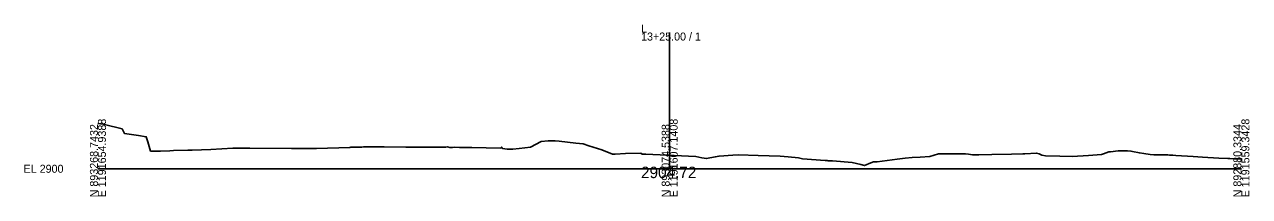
# Model space of a CAD drawing. Extents: x 1791751 to 1799722, y 648637 to 665635.
# Drawn here: x 1792163.2 to 1792591.7, y 655530.3 to 655590.5 of the extents above; entities that cross this region are included whole.
import ezdxf

# ---------------------------------------------------------------- set-up
doc = ezdxf.new("R2010")
doc.units = 0
for name, color, linetype in [('Exist Cross Section Cell', 7, 'Continuous'), ('Exist XS Center Line Elevation Label', 7, 'Continuous'), ('Exist XS Ground Line', 7, 'Continuous')]:
    doc.layers.add(name, color=color, linetype=linetype)

msp = doc.modelspace()

# ---------------------------------------------------------------- linework, layer by layer
at = {"layer": 'Exist Cross Section Cell'}
for p, q in [((1792388.88, 655540.04), (1792388.88, 655587.66)), ((1792388.88, 655540.04), (1792388.88, 655587.66)), ((1792388.88, 655540.04), (1792388.88, 655587.66)), ((1792188.88, 655540.04), (1792388.88, 655540.04)), ((1792188.88, 655540.04), (1792388.88, 655540.04)), ((1792188.88, 655540.04), (1792388.88, 655540.04)), ((1792388.88, 655540.04), (1792588.88, 655540.04)), ((1792388.88, 655540.04), (1792588.88, 655540.04)), ((1792388.88, 655540.04), (1792588.88, 655540.04))]:
    msp.add_line(p, q, dxfattribs=at)
at = {"layer": 'Exist XS Ground Line'}
msp.add_lwpolyline([(1792188.88, 655555.91), (1792190.69, 655555.58), (1792191.19, 655555.46), (1792197.34, 655554.04), (1792198.19, 655552.33), (1792203.02, 655551.62), (1792205.76, 655551.25), (1792206.32, 655549.47), (1792207.31, 655546.21), (1792209.95, 655546.14), (1792210.81, 655546.14), (1792214.08, 655546.32), (1792215.32, 655546.42), (1792220.34, 655546.52), (1792221.87, 655546.58), (1792228.4, 655546.77), (1792236.07, 655547.19), (1792241.98, 655547.23), (1792256.58, 655547.06), (1792257.59, 655547.06), (1792261.05, 655547.1), (1792262.05, 655547.1), (1792264.31, 655547.12), (1792265.39, 655547.11), (1792276.94, 655547.51), (1792277.36, 655547.53), (1792278.62, 655547.55), (1792279.03, 655547.56), (1792280.07, 655547.55), (1792280.6, 655547.56), (1792281.19, 655547.56), (1792281.83, 655547.65), (1792282.95, 655547.65), (1792284.05, 655547.66), (1792285.36, 655547.65), (1792286.45, 655547.65), (1792287.62, 655547.66), (1792288.99, 655547.65), (1792296.59, 655547.63), (1792297.22, 655547.62), (1792297.83, 655547.62), (1792305.24, 655547.56), (1792305.88, 655547.56), (1792310.51, 655547.53), (1792311.19, 655547.67), (1792311.93, 655547.52), (1792312.93, 655547.52), (1792313.51, 655547.53), (1792315.32, 655547.49), (1792316.92, 655547.46), (1792319.62, 655547.42), (1792329.68, 655547.2), (1792330.08, 655547.64), (1792330.42, 655547.06), (1792332.02, 655546.88), (1792332.54, 655546.9), (1792334.01, 655546.88), (1792336.18, 655547.17), (1792340.24, 655547.64), (1792343.93, 655549.58), (1792346.33, 655549.82), (1792348.82, 655549.79), (1792350.24, 655549.69), (1792356.06, 655549.04), (1792358.6, 655548.75), (1792360.59, 655548.03), (1792365.1, 655546.65), (1792368.9, 655545.11), (1792369.77, 655545.15), (1792373.45, 655545.32), (1792378.85, 655545.52), (1792379.31, 655545.17), (1792379.63, 655545.17), (1792380.54, 655545.14), (1792388.01, 655544.8), (1792389.15, 655544.75), (1792390.44, 655544.68), (1792398.01, 655544.3), (1792400.09, 655543.87), (1792401.81, 655543.59), (1792404.81, 655544.18), (1792406.16, 655544.46), (1792411.01, 655544.76), (1792412.91, 655544.88), (1792419.89, 655544.65), (1792427.57, 655544.44), (1792430.34, 655544.18), (1792434, 655543.84), (1792435.3, 655543.53), (1792443.25, 655542.93), (1792443.97, 655542.91), (1792444.38, 655542.85), (1792445.79, 655542.78), (1792452.7, 655542.25), (1792455.71, 655541.53), (1792457.01, 655541.16), (1792459.28, 655542.08), (1792460.17, 655542.43), (1792461.43, 655542.51), (1792468.47, 655543.34), (1792471.23, 655543.71), (1792473.66, 655543.92), (1792476.51, 655544.14), (1792479.9, 655544.28), (1792482.96, 655545.22), (1792490.25, 655545.28), (1792492.33, 655545.29), (1792493.4, 655545.13), (1792494.81, 655544.95), (1792497, 655544.9), (1792501.58, 655544.99), (1792508.45, 655545.16), (1792512.38, 655545.26), (1792513.16, 655545.29), (1792517.26, 655545.51), (1792518.11, 655545.2), (1792519.08, 655544.83), (1792520.39, 655544.5), (1792525.38, 655544.48), (1792529.66, 655544.34), (1792535.37, 655544.72), (1792539.93, 655545.03), (1792540.26, 655545.16), (1792540.66, 655545.26), (1792542.52, 655545.92), (1792543.05, 655545.99), (1792545.79, 655546.29), (1792549.09, 655546.27), (1792550.26, 655546.21), (1792550.75, 655546.11), (1792553.2, 655545.58), (1792554.74, 655545.33), (1792557.01, 655545.04), (1792558.29, 655544.85), (1792563.12, 655544.85), (1792563.76, 655544.8), (1792564.86, 655544.74), (1792565.9, 655544.68), (1792571.98, 655544.31), (1792575.31, 655544.14), (1792580.95, 655543.76), (1792584.14, 655543.62), (1792584.89, 655543.57), (1792586.21, 655543.53), (1792588.88, 655543.52)], dxfattribs=at)
msp.add_lwpolyline([(1792188.88, 655555.91), (1792190.69, 655555.58), (1792191.19, 655555.46), (1792197.34, 655554.04), (1792198.19, 655552.33), (1792203.02, 655551.62), (1792205.76, 655551.25), (1792206.32, 655549.47), (1792207.31, 655546.21), (1792209.95, 655546.14), (1792210.81, 655546.14), (1792214.08, 655546.32), (1792215.32, 655546.42), (1792220.34, 655546.52), (1792221.87, 655546.58), (1792228.4, 655546.77), (1792236.07, 655547.19), (1792241.98, 655547.23), (1792256.58, 655547.06), (1792257.59, 655547.06), (1792261.05, 655547.1), (1792262.05, 655547.1), (1792264.31, 655547.12), (1792265.39, 655547.11), (1792276.94, 655547.51), (1792277.36, 655547.53), (1792278.62, 655547.55), (1792279.03, 655547.56), (1792280.07, 655547.55), (1792280.6, 655547.56), (1792281.19, 655547.56), (1792281.83, 655547.65), (1792282.95, 655547.65), (1792284.05, 655547.66), (1792285.36, 655547.65), (1792286.45, 655547.65), (1792287.62, 655547.66), (1792288.99, 655547.65), (1792296.59, 655547.63), (1792297.22, 655547.62), (1792297.83, 655547.62), (1792305.24, 655547.56), (1792305.88, 655547.56), (1792310.51, 655547.53), (1792311.19, 655547.67), (1792311.93, 655547.52), (1792312.93, 655547.52), (1792313.51, 655547.53), (1792315.32, 655547.49), (1792316.92, 655547.46), (1792319.62, 655547.42), (1792329.68, 655547.2), (1792330.08, 655547.64), (1792330.42, 655547.06), (1792332.02, 655546.88), (1792332.54, 655546.9), (1792334.01, 655546.88), (1792336.18, 655547.17), (1792340.24, 655547.64), (1792343.93, 655549.58), (1792346.33, 655549.82), (1792348.82, 655549.79), (1792350.24, 655549.69), (1792356.06, 655549.04), (1792358.6, 655548.75), (1792360.59, 655548.03), (1792365.1, 655546.65), (1792368.9, 655545.11), (1792369.77, 655545.15), (1792373.45, 655545.32), (1792378.85, 655545.52), (1792379.31, 655545.17), (1792379.63, 655545.17), (1792380.54, 655545.14), (1792388.01, 655544.8), (1792389.15, 655544.75), (1792390.44, 655544.68), (1792398.01, 655544.3), (1792400.09, 655543.87), (1792401.81, 655543.59), (1792404.81, 655544.18), (1792406.16, 655544.46), (1792411.01, 655544.76), (1792412.91, 655544.88), (1792419.89, 655544.65), (1792427.57, 655544.44), (1792430.34, 655544.18), (1792434, 655543.84), (1792435.3, 655543.53), (1792443.25, 655542.93), (1792443.97, 655542.91), (1792444.38, 655542.85), (1792445.79, 655542.78), (1792452.7, 655542.25), (1792455.71, 655541.53), (1792457.01, 655541.16), (1792459.28, 655542.08), (1792460.17, 655542.43), (1792461.43, 655542.51), (1792468.47, 655543.34), (1792471.23, 655543.71), (1792473.66, 655543.92), (1792476.51, 655544.14), (1792479.9, 655544.28), (1792482.96, 655545.22), (1792490.25, 655545.28), (1792492.33, 655545.29), (1792493.4, 655545.13), (1792494.81, 655544.95), (1792497, 655544.9), (1792501.58, 655544.99), (1792508.45, 655545.16), (1792512.38, 655545.26), (1792513.16, 655545.29), (1792517.26, 655545.51), (1792518.11, 655545.2), (1792519.08, 655544.83), (1792520.39, 655544.5), (1792525.38, 655544.48), (1792529.66, 655544.34), (1792535.37, 655544.72), (1792539.93, 655545.03), (1792540.26, 655545.16), (1792540.66, 655545.26), (1792542.52, 655545.92), (1792543.05, 655545.99), (1792545.79, 655546.29), (1792549.09, 655546.27), (1792550.26, 655546.21), (1792550.75, 655546.11), (1792553.2, 655545.58), (1792554.74, 655545.33), (1792557.01, 655545.04), (1792558.29, 655544.85), (1792563.12, 655544.85), (1792563.76, 655544.8), (1792564.86, 655544.74), (1792565.9, 655544.68), (1792571.98, 655544.31), (1792575.31, 655544.14), (1792580.95, 655543.76), (1792584.14, 655543.62), (1792584.89, 655543.57), (1792586.21, 655543.53), (1792588.88, 655543.52)], dxfattribs=at)
msp.add_lwpolyline([(1792188.88, 655555.91), (1792190.69, 655555.58), (1792191.19, 655555.46), (1792197.34, 655554.04), (1792198.19, 655552.33), (1792203.02, 655551.62), (1792205.76, 655551.25), (1792206.32, 655549.47), (1792207.31, 655546.21), (1792209.95, 655546.14), (1792210.81, 655546.14), (1792214.08, 655546.32), (1792215.32, 655546.42), (1792220.34, 655546.52), (1792221.87, 655546.58), (1792228.4, 655546.77), (1792236.07, 655547.19), (1792241.98, 655547.23), (1792256.58, 655547.06), (1792257.59, 655547.06), (1792261.05, 655547.1), (1792262.05, 655547.1), (1792264.31, 655547.12), (1792265.39, 655547.11), (1792276.94, 655547.51), (1792277.36, 655547.53), (1792278.62, 655547.55), (1792279.03, 655547.56), (1792280.07, 655547.55), (1792280.6, 655547.56), (1792281.19, 655547.56), (1792281.83, 655547.65), (1792282.95, 655547.65), (1792284.05, 655547.66), (1792285.36, 655547.65), (1792286.45, 655547.65), (1792287.62, 655547.66), (1792288.99, 655547.65), (1792296.59, 655547.63), (1792297.22, 655547.62), (1792297.83, 655547.62), (1792305.24, 655547.56), (1792305.88, 655547.56), (1792310.51, 655547.53), (1792311.19, 655547.67), (1792311.93, 655547.52), (1792312.93, 655547.52), (1792313.51, 655547.53), (1792315.32, 655547.49), (1792316.92, 655547.46), (1792319.62, 655547.42), (1792329.68, 655547.2), (1792330.08, 655547.64), (1792330.42, 655547.06), (1792332.02, 655546.88), (1792332.54, 655546.9), (1792334.01, 655546.88), (1792336.18, 655547.17), (1792340.24, 655547.64), (1792343.93, 655549.58), (1792346.33, 655549.82), (1792348.82, 655549.79), (1792350.24, 655549.69), (1792356.06, 655549.04), (1792358.6, 655548.75), (1792360.59, 655548.03), (1792365.1, 655546.65), (1792368.9, 655545.11), (1792369.77, 655545.15), (1792373.45, 655545.32), (1792378.85, 655545.52), (1792379.31, 655545.17), (1792379.63, 655545.17), (1792380.54, 655545.14), (1792388.01, 655544.8), (1792389.15, 655544.75), (1792390.44, 655544.68), (1792398.01, 655544.3), (1792400.09, 655543.87), (1792401.81, 655543.59), (1792404.81, 655544.18), (1792406.16, 655544.46), (1792411.01, 655544.76), (1792412.91, 655544.88), (1792419.89, 655544.65), (1792427.57, 655544.44), (1792430.34, 655544.18), (1792434, 655543.84), (1792435.3, 655543.53), (1792443.25, 655542.93), (1792443.97, 655542.91), (1792444.38, 655542.85), (1792445.79, 655542.78), (1792452.7, 655542.25), (1792455.71, 655541.53), (1792457.01, 655541.16), (1792459.28, 655542.08), (1792460.17, 655542.43), (1792461.43, 655542.51), (1792468.47, 655543.34), (1792471.23, 655543.71), (1792473.66, 655543.92), (1792476.51, 655544.14), (1792479.9, 655544.28), (1792482.96, 655545.22), (1792490.25, 655545.28), (1792492.33, 655545.29), (1792493.4, 655545.13), (1792494.81, 655544.95), (1792497, 655544.9), (1792501.58, 655544.99), (1792508.45, 655545.16), (1792512.38, 655545.26), (1792513.16, 655545.29), (1792517.26, 655545.51), (1792518.11, 655545.2), (1792519.08, 655544.83), (1792520.39, 655544.5), (1792525.38, 655544.48), (1792529.66, 655544.34), (1792535.37, 655544.72), (1792539.93, 655545.03), (1792540.26, 655545.16), (1792540.66, 655545.26), (1792542.52, 655545.92), (1792543.05, 655545.99), (1792545.79, 655546.29), (1792549.09, 655546.27), (1792550.26, 655546.21), (1792550.75, 655546.11), (1792553.2, 655545.58), (1792554.74, 655545.33), (1792557.01, 655545.04), (1792558.29, 655544.85), (1792563.12, 655544.85), (1792563.76, 655544.8), (1792564.86, 655544.74), (1792565.9, 655544.68), (1792571.98, 655544.31), (1792575.31, 655544.14), (1792580.95, 655543.76), (1792584.14, 655543.62), (1792584.89, 655543.57), (1792586.21, 655543.53), (1792588.88, 655543.52)], dxfattribs=at)

# ---------------------------------------------------------------- texts
at = {"layer": 'Exist Cross Section Cell'}
for s, p in [('13+25.00 / 1', (1792378.88, 655584.86)), ('13+25.00 / 1', (1792378.88, 655584.86)), ('13+25.00 / 1', (1792378.88, 655584.86)), ('L', (1792378.88, 655587.66)), ('L', (1792378.88, 655587.66)), ('L', (1792378.88, 655587.66)), ('EL 2900', (1792162.88, 655538.64)), ('EL 2900', (1792162.88, 655538.64)), ('EL 2900', (1792162.88, 655538.64))]:
    msp.add_text(s, height=2.8, dxfattribs=at).set_placement(p)
for s, p in [('E 1191654.9388', (1792191.68, 655530.04)), ('E 1191654.9388', (1792191.68, 655530.04)), ('E 1191654.9388', (1792191.68, 655530.04)), ('E 1191607.1408', (1792391.68, 655530.04)), ('E 1191607.1408', (1792391.68, 655530.04)), ('E 1191607.1408', (1792391.68, 655530.04)), ('E 1191559.3428', (1792591.68, 655530.04)), ('E 1191559.3428', (1792591.68, 655530.04)), ('E 1191559.3428', (1792591.68, 655530.04)), ('N 893268.7432', (1792188.88, 655530.04)), ('N 893268.7432', (1792188.88, 655530.04)), ('N 893268.7432', (1792188.88, 655530.04)), ('N 893074.5388', (1792388.88, 655530.04)), ('N 893074.5388', (1792388.88, 655530.04)), ('N 893074.5388', (1792388.88, 655530.04)), ('N 892880.3344', (1792588.88, 655530.04)), ('N 892880.3344', (1792588.88, 655530.04)), ('N 892880.3344', (1792588.88, 655530.04))]:
    msp.add_text(s, height=2.8, rotation=90, dxfattribs=at).set_placement(p)
at = {"layer": 'Exist XS Center Line Elevation Label'}
for height, p in [(4, (1792378.87, 655536.76)), (4, (1792378.87, 655536.76)), (1, (1792386.42, 655539.76))]:
    msp.add_text('2904.72', height=height, dxfattribs=at).set_placement(p)

doc.saveas('drawing.dxf')
